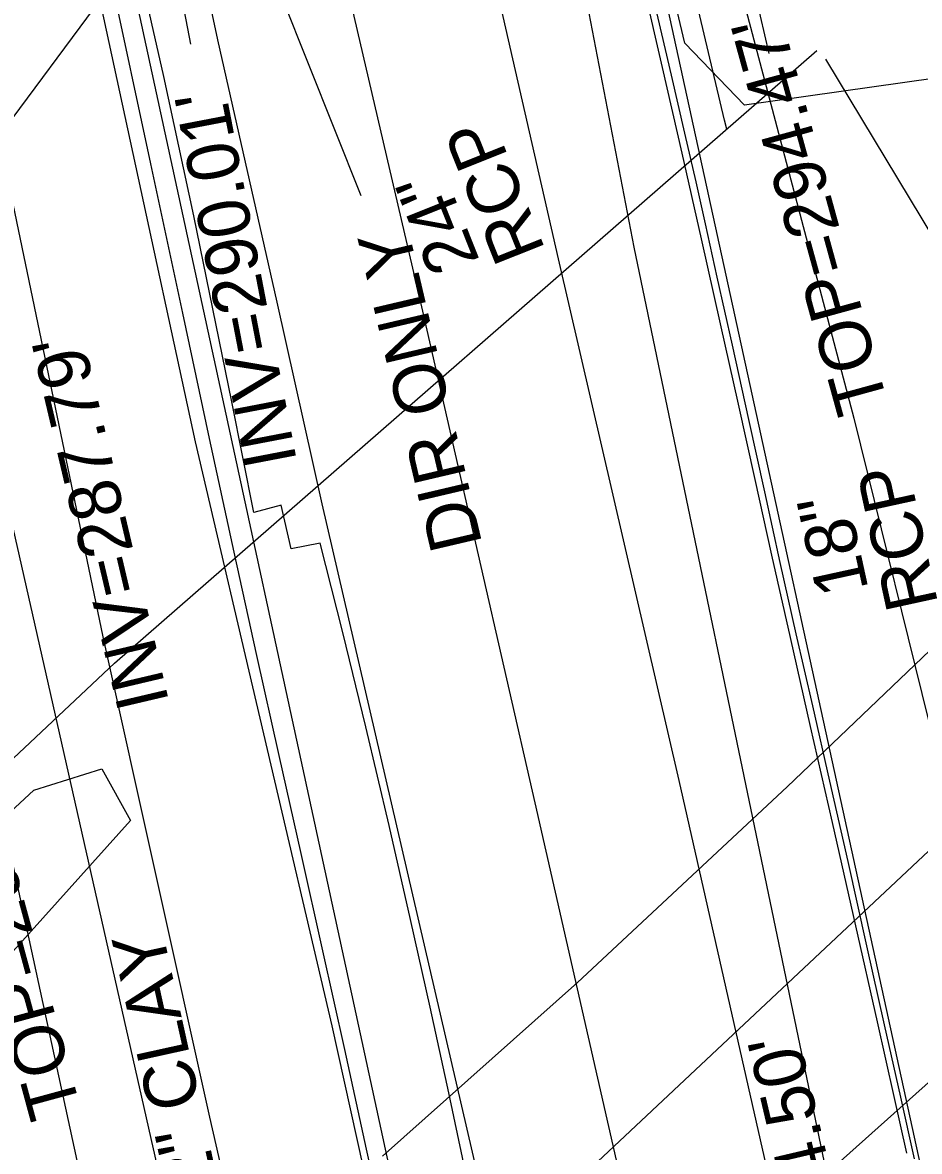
# Model space of a CAD drawing. Extents: x 2100323 to 2109811, y 740376 to 749755.
# Drawn here: x 2105960.4 to 2106029.5, y 740959.3 to 741046.3 of the extents above; entities that cross this region are included whole.
import ezdxf

# ---------------------------------------------------------------- set-up
doc = ezdxf.new("R2010")
doc.units = 0
for name, color, linetype in [('Exist Horizontal Alignment', 7, 'Continuous'), ('Exist Railroads Standard Gauge', 7, 'Continuous'), ('Exist Roads Curbs', 7, 'Continuous'), ('Exist Roads EOP', 7, 'Continuous'), ('Exist Roads EOP Other', 7, 'Continuous'), ('Exist Roads EOT', 7, 'Continuous'), ('Exist Structure Major Bridge WW', 7, 'Continuous'), ('Exist Structure Major Deck Tunnel Box Culvert', 7, 'Continuous'), ('Exist Structure Minor Catch Basin Top Elevation', 7, 'Continuous'), ('Exist Structure Minor Pipes RCP 15 Inch', 7, 'Continuous'), ('Exist Structure Minor Pipes RCP 15 Inch Invert', 7, 'Continuous'), ('Exist Structure Minor Pipes RCP 18 Inch', 7, 'Continuous'), ('Exist Structure Minor Pipes RCP 18 Inch Text', 7, 'Continuous'), ('Exist Structure Minor Pipes RCP 24 Inch', 7, 'Continuous'), ('Exist Structure Minor Pipes RCP 24 Inch Invert', 7, 'Continuous'), ('Exist Structure Minor Pipes RCP 24 Inch Text', 7, 'Continuous'), ('Exist Utilities Sanitary Sewer UG Line', 7, 'Continuous'), ('Exist Utilities Sanitary Sewer UG Line Invert Elevation', 7, 'Continuous'), ('Exist Utilities Sanitary Sewer UG Line Text', 7, 'Continuous'), ('Exist Utilities Telephone UG Conduit SUE LOS B', 7, 'Continuous'), ('Exist Utilities Telephone UG FO SUE LOS C', 7, 'Continuous'), ('Exist Utilities Water UG Line SUE LOS B', 7, 'Continuous'), ('Exist Vegetation Woods Line', 7, 'Continuous')]:
    doc.layers.add(name, color=color, linetype=linetype)

msp = doc.modelspace()

# ---------------------------------------------------------------- linework, layer by layer
at = {"layer": 'Exist Horizontal Alignment'}
msp.add_line((2106006.28, 740876.828), (2105895.132, 741389.499), dxfattribs=at)
at = {"layer": 'Exist Railroads Standard Gauge'}
msp.add_lwpolyline([(2105988.123, 740958.929), (2106003.164, 740972.328), (2106019.317, 740987.407), (2106033.237, 741000.69), (2106049.246, 741016.947), (2106063.494, 741031.724), (2106076.478, 741045.675), (2106088.968, 741059.618), (2106101.131, 741073.521), (2106111.712, 741086.193), (2106123.733, 741100.636), (2106137.592, 741117.927), (2106149.749, 741134.137), (2106161.897, 741150.506), (2106175, 741168.905), (2106188.341, 741188.681), (2106200.28, 741206.925), (2106211.051, 741223.805), (2106220.821, 741239.629), (2106230.377, 741255.748), (2106241.731, 741275.772), (2106253.848, 741298.027), (2106264.202, 741318.224), (2106275.256, 741340.483)], dxfattribs=at)
at = {"layer": 'Exist Roads Curbs'}
msp.add_lwpolyline([(2106029.136, 740958.723), (2106028.078, 740963.486), (2106026.838, 740969.047), (2106025.477, 740975.139), (2106024.022, 740981.644), (2106022.618, 740987.853), (2106021.291, 740993.649), (2106020.022, 740999.208), (2106018.793, 741004.705), (2106017.595, 741010.166), (2106016.366, 741015.744), (2106015.098, 741021.465), (2106013.934, 741026.7), (2106013.019, 741030.821), (2106012.298, 741034.059), (2106011.445, 741037.806), (2106010.403, 741042.295), (2106009.202, 741047.459)], dxfattribs=at)
at = {"layer": 'Exist Roads EOP'}
for points in [[(2105988.587, 740951.832), (2105986.897, 740959.459), (2105985.212, 740967.146), (2105983.528, 740974.76), (2105981.845, 740982.277), (2105980.152, 740989.827), (2105978.439, 740997.536), (2105976.687, 741005.497), (2105974.785, 741014.267), (2105972.714, 741023.938), (2105970.258, 741035.457), (2105967.197, 741049.77), (2105965.441, 741057.974), (2105963.662, 741066.284), (2105960.425, 741081.443), (2105957.613, 741094.655), (2105954.941, 741107.264), (2105952.124, 741120.61)], [(2105994.68, 740956.996), (2105993.233, 740963.803), (2105991.794, 740970.421), (2105990.285, 740977.182), (2105988.627, 740984.42), (2105986.841, 740992.023), (2105985.062, 740999.319), (2105983.311, 741006.196), (2105981.082, 741005.754), (2105980.308, 741009.115), (2105978.209, 741008.567), (2105976.511, 741017.086), (2105973.579, 741031.426), (2105971.264, 741042.171), (2105969.371, 741050.598)], [(2106028.546, 740959.161), (2106027.577, 740963.521), (2106026.284, 740969.283), (2106024.612, 740976.693), (2106022.809, 740984.65), (2106021.128, 740992.053), (2106019.569, 740998.91), (2106018.141, 741005.261), (2106016.844, 741011.113), (2106015.564, 741016.914), (2106014.185, 741023.11), (2106012.716, 741029.655), (2106011.221, 741036.263), (2106009.711, 741042.886), (2106008.275, 741049.137)]]:
    msp.add_lwpolyline(points, dxfattribs=at)
at = {"layer": 'Exist Roads EOP Other'}
msp.add_line((2105983.117, 741192.015), (2106017.917, 741043.942), dxfattribs=at)
msp.add_lwpolyline([(2106014.658, 741038.132), (2106014.486, 741038.811), (2105994.974, 741121.34), (2105989.469, 741144.626), (2105983.96, 741167.913), (2105978.39, 741191.048), (2105973.397, 741212.678), (2105969.561, 741229.948), (2105966.297, 741244.201), (2105964.069, 741255.269), (2105962.978, 741258.031), (2105961.939, 741259.43), (2105961.216, 741260.138)], dxfattribs=at)
at = {"layer": 'Exist Roads EOT'}
for points in [[(2105890.846, 741349.335), (2105899.432, 741309.704), (2105908.147, 741270.242), (2105916.616, 741231.659), (2105925.02, 741193.008), (2105933.585, 741153.59), (2105941.665, 741116.136), (2105950.104, 741077.074), (2105958.397, 741038.167), (2105966.547, 740998.978), (2105974.788, 740961.942), (2105983.851, 740922.306), (2105991.887, 740882.238), (2105995.873, 740842.797), (2105992.71, 740801.767), (2105978.277, 740756.909), (2105971.197, 740741.935), (2105964.095, 740728.984), (2105953.18, 740711.232), (2105942.499, 740696.213), (2105929.601, 740680.649), (2105916.153, 740666.014), (2105888.786, 740636.954), (2105887.605, 740635.562)], [(2105902.159, 741342.251), (2105909.402, 741308.247), (2105917.986, 741271.654), (2105925.981, 741234.451), (2105934.723, 741194.125), (2105943.735, 741151.716), (2105953.122, 741110.019), (2105963.664, 741060.392), (2105973.667, 741014.016), (2105984.215, 740968.981), (2105995.186, 740919.297), (2106000.912, 740890.669), (2106002.5, 740884.502), (2106004.272, 740876.247), (2106005.705, 740867.464), (2106007.008, 740858.77), (2106007.783, 740852.704), (2106008.829, 740843.65)], [(2105930.026, 741337.012), (2105939.252, 741297.237), (2105948.285, 741258.28), (2105957.072, 741219.768), (2105965.865, 741181.872), (2105975.192, 741142.04), (2105984.519, 741102.567), (2105993, 741066.083), (2106001.657, 741028.122), (2106010.966, 740987.903), (2106019.769, 740949.053), (2106028.416, 740911.773), (2106038.248, 740872.778), (2106043.444, 740855.882), (2106050.161, 740838.313), (2106058.332, 740820.591), (2106067.404, 740804.734), (2106075.259, 740793.076), (2106085.445, 740780.815), (2106098.964, 740767.083), (2106115.061, 740753.419), (2106130.433, 740741.631), (2106131.984, 740740.541)], [(2105919.718, 741333.801), (2105928.578, 741295.107), (2105937.39, 741256.247), (2105946.52, 741217.048), (2105955.079, 741178.875), (2105964.224, 741140.208), (2105972.915, 741102.489), (2105982.074, 741063.318), (2105991.116, 741024.419), (2105999.859, 740986.178), (2106008.815, 740946.882), (2106017.181, 740909.61), (2106025.941, 740872.266), (2106030.264, 740856.136), (2106037.817, 740832.925), (2106046.848, 740813.934), (2106056.516, 740796.779), (2106067.856, 740781.41), (2106078.375, 740769.296), (2106093.108, 740755.235), (2106107.907, 740742.891), (2106125.012, 740730.623)], [(2105998.363, 740945.042), (2105983.478, 741009.218), (2105980.002, 741024.778), (2105975.437, 741045.014), (2105970.284, 741069.082), (2105963.614, 741097.135), (2105959.573, 741114.682), (2105954.306, 741137.792), (2105949.121, 741160.719), (2105943.511, 741184.386), (2105938.431, 741206.753), (2105933.846, 741226.036), (2105927.192, 741255.195), (2105921.72, 741278.469), (2105915.819, 741303.532), (2105909.615, 741331.186)], [(2105884.458, 741327.17), (2105889.032, 741306.325), (2105897.404, 741268.101), (2105905.961, 741229.52), (2105914.206, 741191.35), (2105922.67, 741151.86), (2105931.018, 741113.223), (2105939.342, 741075.347), (2105947.597, 741036.734), (2105955.91, 740998.365), (2105964.546, 740958.588)]]:
    msp.add_lwpolyline(points, dxfattribs=at)
at = {"layer": 'Exist Structure Major Bridge WW'}
msp.add_lwpolyline([(2106057.079, 740985.06), (2106055.695, 740988.189), (2106022.312, 741043.53)], dxfattribs=at)
at = {"layer": 'Exist Structure Major Deck Tunnel Box Culvert'}
msp.add_lwpolyline([(2106055.634, 740987.34), (2105937.68, 740881.899), (2105922.326, 740954.512), (2105967.458, 740996.938), (2106021.602, 741044.192)], dxfattribs=at)
at = {"layer": 'Exist Structure Minor Pipes RCP 15 Inch'}
msp.add_line((2105975.486, 741060.438), (2105937.571, 741009.301), dxfattribs=at)
at = {"layer": 'Exist Structure Minor Pipes RCP 18 Inch'}
msp.add_line((2106041.411, 740904.184), (2106006.126, 741065.74), dxfattribs=at)
at = {"layer": 'Exist Structure Minor Pipes RCP 24 Inch'}
msp.add_line((2105975.511, 741060.433), (2105986.446, 741033.007), dxfattribs=at)
at = {"layer": 'Exist Structure Minor Pipes RCP 24 Inch Invert'}
msp.add_lwpolyline([(2105975.511, 741060.433), (2105972.178, 741050.575), (2105973.31, 741044.683)], dxfattribs=at)
at = {"layer": 'Exist Utilities Sanitary Sewer UG Line'}
msp.add_line((2106015.589, 740759.993), (2105954.862, 741028.478), dxfattribs=at)
at = {"layer": 'Exist Utilities Telephone UG Conduit SUE LOS B'}
msp.add_lwpolyline([(2105948.526, 741350.732), (2105951.288, 741339.36), (2105955.469, 741311.983), (2105960.35, 741280.196), (2105964.972, 741257.117), (2105966.75, 741243.789), (2105975.013, 741211.176), (2105983.416, 741177.939), (2105988.125, 741158.568), (2105993.812, 741135.109), (2106000.574, 741106.295), (2106009.349, 741073.929), (2106016.042, 741047.733), (2106024.473, 741015.836), (2106030.771, 740990.332)], dxfattribs=at)
at = {"layer": 'Exist Utilities Telephone UG FO SUE LOS C'}
msp.add_lwpolyline([(2105810.196, 740818.093), (2105917.922, 740884.546), (2105963.668, 740919.987), (2106050.734, 741001.699), (2106123.043, 741079.966), (2106174.046, 741146.234), (2106228.155, 741228.439), (2106289.703, 741341.747), (2106325.612, 741424.936), (2106347.501, 741497.572), (2106369.144, 741594.052), (2106385.254, 741705.914), (2106392.571, 741937.329), (2106389.62, 742143.579)], dxfattribs=at)
at = {"layer": 'Exist Utilities Water UG Line SUE LOS B'}
msp.add_lwpolyline([(2106094.019, 740794.493), (2106083.681, 740806.602), (2106061.906, 740841.846), (2106047.424, 740864.106), (2106027.441, 740933.211), (2106007.515, 741029.026), (2105993.515, 741101.898), (2105977.09, 741185.433), (2105973.671, 741208.653), (2105971.837, 741262.635), (2105977.085, 741334.052), (2105976.937, 741358.177), (2105974.307, 741389.692), (2105969.212, 741418.162), (2105954.113, 741497.092)], dxfattribs=at)
at = {"layer": 'Exist Vegetation Woods Line'}
for points in [[(2106122.762, 741120.578), (2106099.889, 741094.485), (2106073.396, 741066.954), (2106055.91, 741049.903), (2106048.846, 741044.528), (2106040.542, 741041.643), (2106030.771, 741042.049), (2106016.024, 741039.965), (2106011.434, 741044.745), (2106004.104, 741075.708), (2105994.633, 741118.328)], [(2105857.476, 740948.979), (2105862.576, 740960.588), (2105866.48, 740972.646), (2105870.359, 740989.37), (2105877.404, 741006.042), (2105883.057, 741016.989), (2105887.201, 741022.159), (2105893.161, 741021.188), (2105899.739, 741016.062), (2105908.756, 741013.823), (2105919.474, 741010.794), (2105926.611, 741005.541), (2105928.648, 740999.053), (2105926.474, 740992.814), (2105920.823, 740980.212), (2105925.542, 740965.139), (2105929.425, 740960.003), (2105949.432, 740976.218), (2105961.238, 740987.147), (2105966.479, 740988.785), (2105968.701, 740984.805), (2105960.136, 740975.279), (2105952.365, 740966.809), (2105949.094, 740956.6)]]:
    msp.add_lwpolyline(points, dxfattribs=at)

# ---------------------------------------------------------------- texts
at = {"layer": 'Exist Structure Minor Catch Basin Top Elevation'}
for s, rotation, p in [("TOP=294.47'", 105.37455, (2106027.141, 741016.809)), ("TOP=294.00'", 105.22385, (2105964.904, 740962.465))]:
    msp.add_text(s, height=4, rotation=rotation, dxfattribs=at).set_placement(p)
at = {"layer": 'Exist Structure Minor Pipes RCP 15 Inch Invert'}
msp.add_text("INV=294.50'", height=4, rotation=103.23438, dxfattribs=at).set_placement((2106026.86, 740940.004))
at = {"layer": 'Exist Structure Minor Pipes RCP 18 Inch Text'}
for s, p in [('RCP', (2106030.978, 741001.51)), ('18"', (2106025.608, 741002.626))]:
    msp.add_text(s, height=4, rotation=102.32034, dxfattribs=at).set_placement(p)
at = {"layer": 'Exist Structure Minor Pipes RCP 24 Inch Invert'}
for s, rotation, p in [("INV=290.01'", 100.87566, (2105981.535, 741012.475)), ('DIR ONLY', 103.21433, (2105995.828, 741006.127))]:
    msp.add_text(s, height=4, rotation=rotation, dxfattribs=at).set_placement(p)
at = {"layer": 'Exist Structure Minor Pipes RCP 24 Inch Text'}
for s, p in [('RCP', (2106000.704, 741028.798)), ('24"', (2105995.644, 741027.967))]:
    msp.add_text(s, height=4, rotation=111.73887, dxfattribs=at).set_placement(p)
at = {"layer": 'Exist Utilities Sanitary Sewer UG Line Invert Elevation'}
msp.add_text("INV=287.79'", height=4, rotation=103.26268, dxfattribs=at).set_placement((2105971.685, 740993.918))
at = {"layer": 'Exist Utilities Sanitary Sewer UG Line Text'}
msp.add_text('12" CLAY', height=4, rotation=102.42227, dxfattribs=at).set_placement((2105976.121, 740953.833))

doc.saveas('drawing.dxf')
